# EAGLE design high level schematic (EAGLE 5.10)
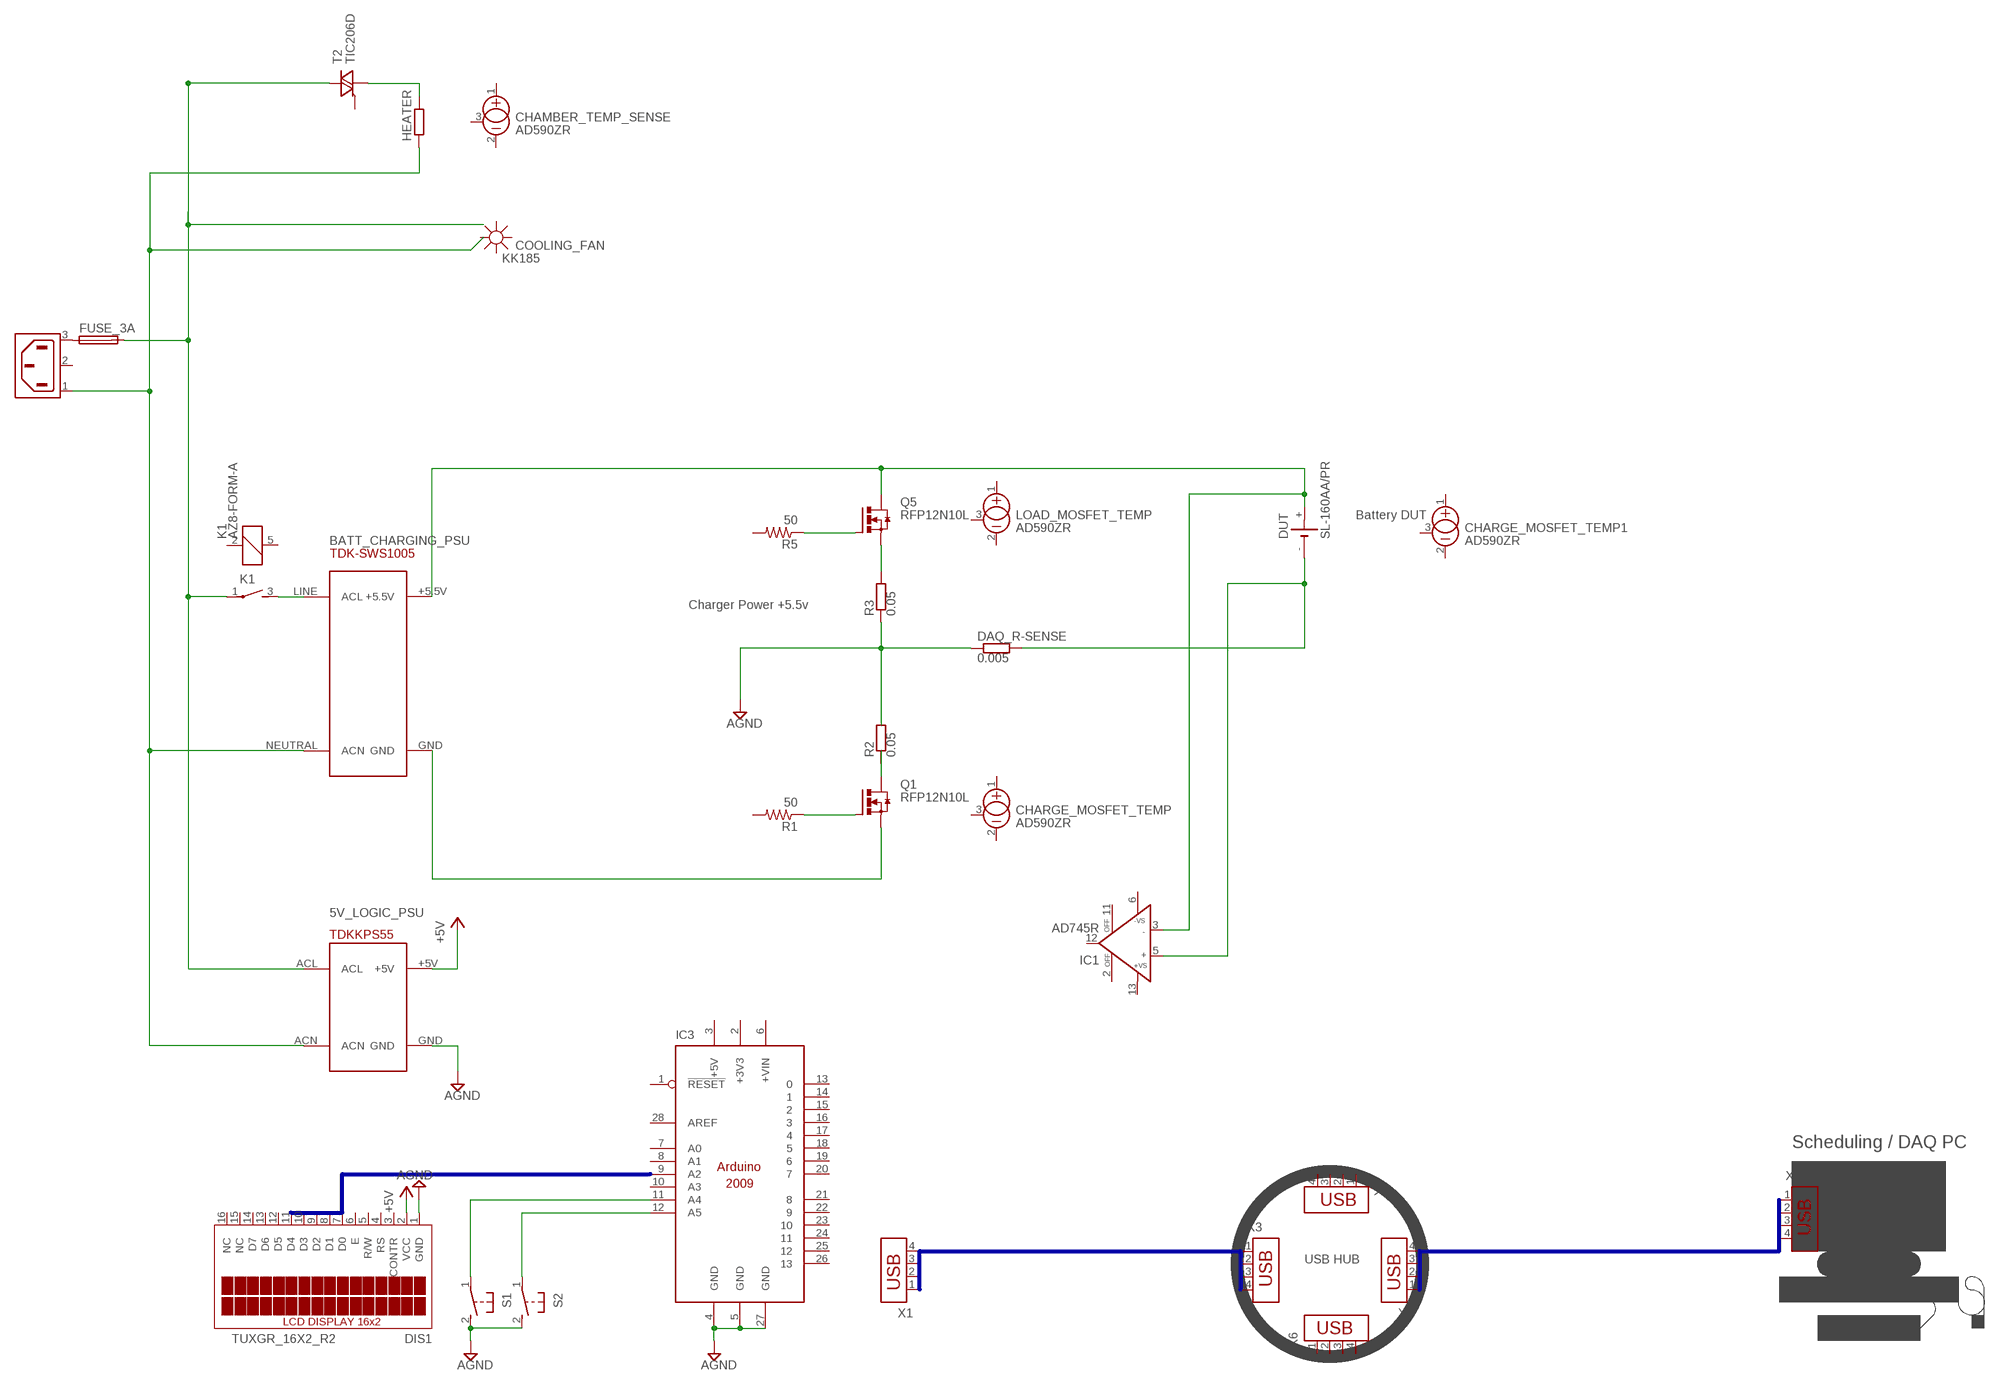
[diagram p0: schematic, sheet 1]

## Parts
5V_LOGIC_PSU  TDKKPS55  [TDKKPS55]
BATT_CHARGING_PSU  TDK-SWS1005  [TDK-SWS1005]
CHAMBER_TEMP_SENSE  AD590ZR  [TO92]
CHARGE_MOSFET_TEMP  AD590ZR  [TO92]
CHARGE_MOSFET_TEMP1  AD590ZR  [TO92]
COOLING_FAN  KK185  [KK185]
DAQ_R-SENSE  0.005  BVS  [BVS]
DIS1  TUXGR_16X2_R2  [TUXGR_16X2_R2]
DUT  SL-160AA/PR  [SL-160AA/PR]
FUSE_3A  KS9V  [KS9V]
HEATER  R-EU_0204/7  [0204/7]
IC1  AD745R  [SOIC16R]
IC3  ARDUINO2009_11  [ARDUINO2009_1]
K1  AZ8-FORM-A  [AZ8]
LOAD_MOSFET_TEMP  AD590ZR  [TO92]
Q1  RFP12N10L  [TO220-W/657-20ABP]
Q5  RFP12N10L  [TO220-W/657-20ABP]
R1  50  R-US_0207/10  [0207/10]
R2  0.05  BVS  [BVS]
R3  0.05  BVS  [BVS]
R5  50  R-US_0207/10  [0207/10]
S1  31-XX  [B3F-31XX]
S2  31-XX  [B3F-31XX]
T2  TIC206D  [TO220BV]
X1  USB-787616  [USB]
X2  6ESRM-P  [6ESRM-P]
X3  USB-787616  [USB]
X4  USB-787616  [USB]
X5  USB-787616  [USB]
X6  USB-787616  [USB]
X7  USB-787616  [USB]

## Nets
+5V: 5V_LOGIC_PSU.+5V DIS1.2(VCC)
AGND: 5V_LOGIC_PSU.GND DAQ_R-SENSE.2 DIS1.1(GND) IC3.4(GND) IC3.5(GND) IC3.27(GND) R3.2 S1.2(S) S2.2(S)
N$1: BATT_CHARGING_PSU.+5.5V DUT.+ IC1.3(IN-) Q5.2(D)
N$2: Q5.3(S) R3.1
N$3: BATT_CHARGING_PSU.LINE(ACL) K1.3(-1:S)
N$4: HEATER.2 T2.T1(A1)
N$5: DAQ_R-SENSE.1 DUT.- IC1.5(IN+)
N$6: Q1.2(D)
N$7: FUSE_3A.1 X2.3(AC2)
N$8: BATT_CHARGING_PSU.GND Q1.3(S)
N$9: 5V_LOGIC_PSU.ACL FUSE_3A.2 K1.1(-1:P) T2.T2(A2)
N$10: Q1.1(G) R1.1
N$11: Q5.1(G) R5.1
N$12: IC3.11(A4) S1.1(P)
N$13: 5V_LOGIC_PSU.ACN BATT_CHARGING_PSU.NEUTRAL(ACN) HEATER.1 X2.1(AC1)
N$14: IC3.12(A5) S2.1(P)
Unconnected: CHAMBER_TEMP_SENSE.1(+) CHAMBER_TEMP_SENSE.2(-) CHAMBER_TEMP_SENSE.3(CAN) CHARGE_MOSFET_TEMP1.1(+) CHARGE_MOSFET_TEMP1.2(-) CHARGE_MOSFET_TEMP1.3(CAN) CHARGE_MOSFET_TEMP.1(+) CHARGE_MOSFET_TEMP.2(-) CHARGE_MOSFET_TEMP.3(CAN) DIS1.3(CONTR) DIS1.4(RS) DIS1.5(R/W) DIS1.6(E) DIS1.7(D0) DIS1.8(D1) DIS1.9(D2) DIS1.10(D3) DIS1.11(D4) DIS1.12(D5) DIS1.13(D6) DIS1.14(D7) DIS1.15(NC) DIS1.16(NC) IC1.2(OFF) IC1.6(-VS) IC1.11(OFF) IC1.12(OUT) IC1.13(+VS) IC3.1(!RESET) IC3.6(+VIN) IC3.7(A0) IC3.8(A1) IC3.9(A2) IC3.10(A3) IC3.13 IC3.14 IC3.15 IC3.16 IC3.17 IC3.18 IC3.19 IC3.20 IC3.21 IC3.22 IC3.23 IC3.24 IC3.25 IC3.26 IC3.28(AREF) K1.2 K1.5 LOAD_MOSFET_TEMP.1(+) LOAD_MOSFET_TEMP.2(-) LOAD_MOSFET_TEMP.3(CAN) R1.2 R2.1 R2.2 R5.2 T2.G X1.1 X1.2 X1.3 X1.4 X2.2(SH) X3.1 X3.2 X3.3 X3.4 X4.1 X4.2 X4.3 X4.4 X5.1 X5.2 X5.3 X5.4 X6.1 X6.2 X6.3 X6.4 X7.1 X7.2 X7.3 X7.4

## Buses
B$1
B$2
B$3

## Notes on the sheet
- Battery DUT
- Charger Power +5.5v
- Scheduling / DAQ PC
- USB HUB

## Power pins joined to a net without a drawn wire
+3V3: IC3.2(+3V3)
+5V: IC3.3(+5V)

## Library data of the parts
5V_LOGIC_PSU = NEWPARTS:TDKKPS55
BATT_CHARGING_PSU = NEWPARTS:TDK-SWS1005
CHAMBER_TEMP_SENSE CHARGE_MOSFET_TEMP CHARGE_MOSFET_TEMP1 LOAD_MOSFET_TEMP = linear:AD590ZR: TEMPERATURE SENSOR current output
COOLING_FAN = heatsink:KK185: HEATSINK
DAQ_R-SENSE R2 R3 = resistor-shunt:BVS: SMD SHUNT RESISTOR
DIS1 = display-lcd:TUXGR_16X2_R2: Tuxgraphics LCD display 16x2 characters reflective, without background light Source: tuxgr_12x2_r2.pdf
DUT = battery:SL-160AA/PR: LI BATTERY Sonnenschein
FUSE_3A = fuse:KS9V: FUSE HOLDER
HEATER = resistor:R-EU_: RESISTOR, European symbol
IC1 = analog-devices:AD745: Ultralow Noise, High Speed, BiFET Op Amp Course: http://www.analog.com/static/imported-files/data_sheets/AD745.pdf
IC3 = arduino:ARDUINO2009_1: The Arduino Duemilanove ("2009") is a microcontroller board based on the ATmega168 or ATmega328. - 14 digital input/output pins (of which 6 can be used as PWM outputs) - 6 analog inputs, a 16 MHz crystal oscillator - USB connection - power jack - ISP header - reset button It contains everything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
K1 = relay:AZ8-FORM-A: MINIATURE PC BOARD RELAY Form A Source: www.azettler.com .. AZ8-1ch-12DSE.PDF
Q1 Q5 = NEWPARTS:RFP12N10L: N-Channel Power MOSFET 100V; 12A; 0,2Ohm< Logic Level
R1 R5 = rcl:R-US_: RESISTOR, American symbol
S1 S2 = switch-omron:31-XX: OMRON SWITCH
T2 = triac:TIC206: TRIAC Source: http://www.bourns.com/pdfs/tic206.pdf
X1 X3-X7 = con-amp:USB-787616: AMP connector
X2 = con-tycoelectronics:6ESRM-P: AC Connector 120/250 VAC Source: http://catalog.tycoelectronics.com .. ENG_DS_1654001_1099_SR_0406.pdf

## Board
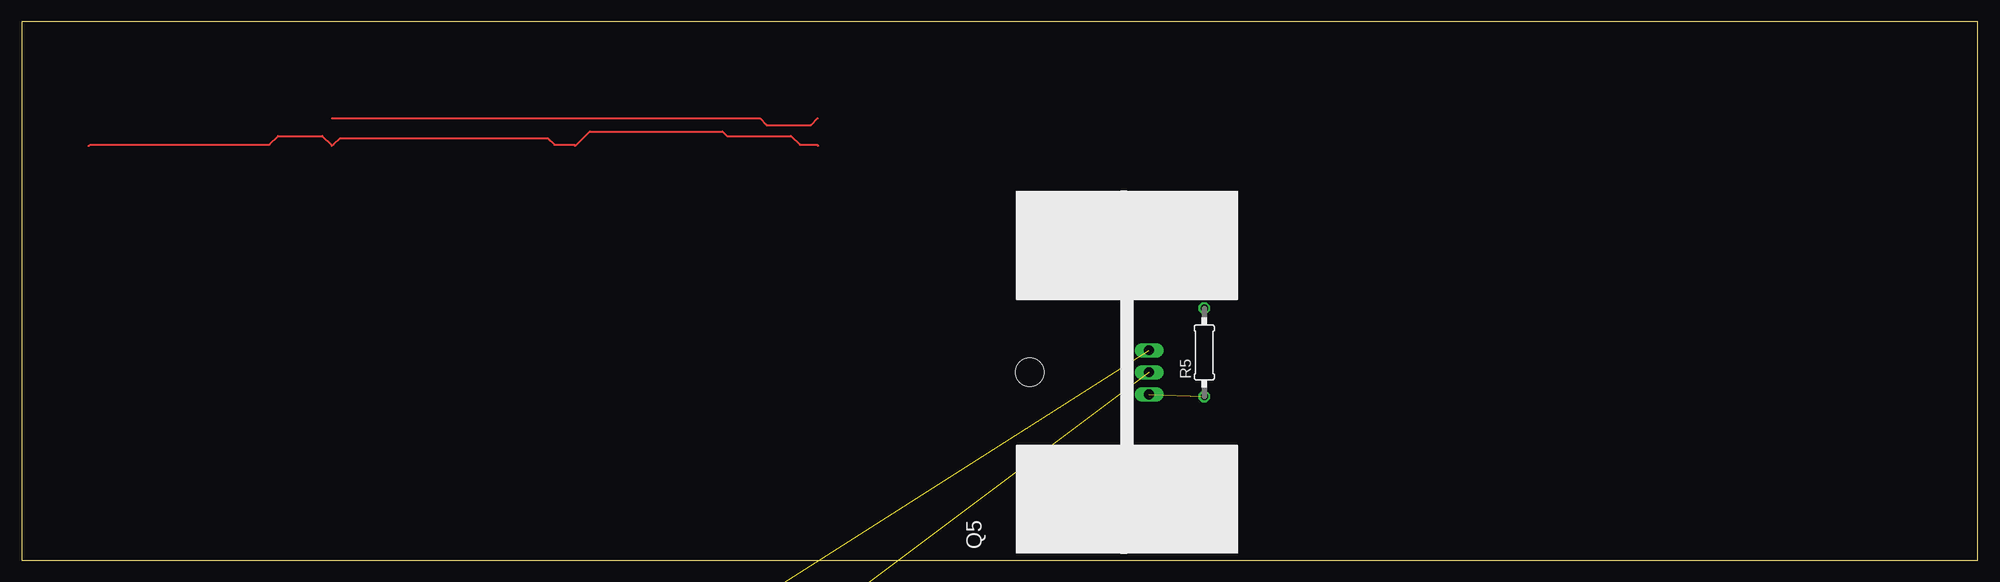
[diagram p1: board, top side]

Size 224.77 x 61.9 mm. Coordinates in mm from the lower left corner, seen from the top.
Outline: 0,0 224.77,0 224.77,61.9 0,61.9 0,0
Copper layers (1*16): Top 0.035mm / dielectric 1.5mm / Bottom 0.035mm
Design rules "default *": minimum track width 10mil, minimum drill 24mil, track to track 10mil, track to pad 10mil, pad to pad 10mil, via to via 10mil, smd to smd 10mil, copper to edge 40mil, drill to drill 10mil, minimum pad ring 10mil, minimum via ring 8mil, stop-mask expansion 4mil, vias tented up to drill 0mil, thermal gap 10mil

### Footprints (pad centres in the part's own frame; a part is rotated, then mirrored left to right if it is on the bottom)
TDKKPS55 = drill 1.1 square: +5V 51,12.5; ACL 4,5; ACN 4,22.5; GND 51,32.5
TDK-SWS1005 = drill 0.8 square: +5.5V 0,-1.27; GND 0,-3.81; LINE 0,5.08; NEUTRAL 0,2.54
TO92 = drill 0.813 octagon: 1 -1.27,0; 2 0,1.905; 3 1.27,0
BVS = smd 2.7 x 6.2: 1 -4.14,0; 2 4.14,0
TUXGR_16X2_R2 = drill 1 pad 1.676 round: 1 -32,15.5; 2 -29.46,15.5; 3 -26.92,15.5; 4 -24.38,15.5; 5 -21.84,15.5; 6 -19.3,15.5; 7 -16.76,15.5; 8 -14.22,15.5; 9 -11.68,15.5; 10 -9.14,15.5; 11 -6.6,15.5; 12 -4.06,15.5; 13 -1.52,15.5; 14 1.02,15.5; 15 3.56,15.5; 16 6.1,15.5 | hole 2.5: -37.5,-15.5; 37.5,-15.5; -37.5,15.5; 37.5,15.5
SL-160AA/PR = drill 1.321 pad 3.15 octagon: + 25.273,0; - -25.4,0
KS9V = drill 1.321 pad 2.54 long: 1 0,3.81; 2 0,-3.81
0204/7 = drill 0.813 octagon: 1 -3.81,0; 2 3.81,0
SOIC16R = smd 0.6 x 2.2: 1 -4.445,-4.775; 2 -3.175,-4.775; 3 -1.905,-4.775; 4 -0.635,-4.775; 5 0.635,-4.775; 6 1.905,-4.775; 7 3.175,-4.775; 8 4.445,-4.775; 9 4.445,4.8; 10 3.175,4.8; 11 1.905,4.8; 12 0.635,4.8; 13 -0.635,4.8; 14 -1.905,4.8; 15 -3.175,4.8; 16 -4.445,4.8
ARDUINO2009_1 = drill 1.016 long: 1 33.02,2.54; 2 35.56,2.54; 3 38.1,2.54; 4 40.64,2.54; 5 43.18,2.54; 6 45.72,2.54; 7 50.8,2.54; 8 53.34,2.54; 9 55.88,2.54; 10 58.42,2.54; 11 60.96,2.54; 12 63.5,2.54; 13 63.5,50.8; 14 60.96,50.8; 15 58.42,50.8; 16 55.88,50.8; 17 53.34,50.8; 18 50.8,50.8; 19 48.26,50.8; 20 45.72,50.8; 21 41.656,50.8; 22 39.116,50.8; 23 36.576,50.8; 24 34.036,50.8; 25 31.496,50.8; 26 28.956,50.8; 27 26.416,50.8; 28 23.876,50.8 | hole 3.2: 15.24,50.8; 66.04,35.56; 66.04,7.62 | hole 2: 55.17,27.114
AZ8 = drill 1.4 pad 2 round: 1 8.89,6.35; 2 -3.81,6.35; 3 -8.89,-1.27; 4 -3.81,-6.35; 5 -8.89,6.35
TO220-W/657-20ABP = drill 1.118 long: 1 -2.54,-2.54; 2 0,-2.54; 3 2.54,-2.54 | drill 2.8 pad 6.452 round: P$1 -12.7,0; P$2 12.7,0 | hole 3.302: 0,11.176
0207/10 = drill 0.813 octagon: 1 -5.08,0; 2 5.08,0
B3F-31XX = drill 1.016 octagon: 1 -2.261,-1.245; 2 2.261,-1.245 | drill 1.499 pad 2.159 round: 3 -3.505,1.245; 4 3.505,1.245
TO220BV = drill 1.016 long: G 2.54,-2.54; T1 -2.54,-2.54; T2 0,-2.54
USB = drill 1 round: 1 -3.5,12.99; 2 -1,12.99; 3 1,12.99; 4 3.5,12.99 | hole 2.3: -6.57,10.28; 6.57,10.28
6ESRM-P = drill 1.6 pad 2.6 round: 1 -9.1,9.7; 2 0,9.7; 3 9.1,9.7 | hole 3.6: -20,0; 20,0

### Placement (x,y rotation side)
5V_LOGIC_PSU  not placed on the board
BATT_CHARGING_PSU  not placed on the board
CHAMBER_TEMP_SENSE  not placed on the board
CHARGE_MOSFET_TEMP  not placed on the board
CHARGE_MOSFET_TEMP1  not placed on the board
COOLING_FAN  not placed on the board
DAQ_R-SENSE  not placed on the board
DIS1  not placed on the board
DUT  not placed on the board
FUSE_3A  not placed on the board
HEATER  not placed on the board
IC1  not placed on the board
IC3  not placed on the board
K1  not placed on the board
LOAD_MOSFET_TEMP  not placed on the board
Q1  not placed on the board
Q5  127,21.59 90 top
R1  not placed on the board
R2  not placed on the board
R3  not placed on the board
R5  135.89,23.88 90 top
S1  not placed on the board
S2  not placed on the board
T2  not placed on the board
X1  not placed on the board
X2  not placed on the board
X3  not placed on the board
X4  not placed on the board
X5  not placed on the board
X6  not placed on the board
X7  not placed on the board

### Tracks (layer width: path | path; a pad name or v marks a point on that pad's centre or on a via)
+5V  (2 unrouted)
AGND  (8 unrouted)
N$1  (3 unrouted)
N$2  (1 unrouted)
N$3  (1 unrouted)
N$4  (1 unrouted)
N$5  (2 unrouted)
N$7  (1 unrouted)
N$8  (1 unrouted)
N$9  (3 unrouted)
N$10  (1 unrouted)
N$11  (1 unrouted)
N$12  (1 unrouted)
N$13  (3 unrouted)
N$14  (1 unrouted)
NC
  Top 0.254: 91.5,47.62 91.44,47.75 89.41,47.75 88.39,48.77 81.03,48.77 80.52,49.28 65.28,49.28 63.75,47.75 63.56,47.62 63.5,47.75 61.21,47.75 60.45,48.51 36.58,48.51 35.81,47.75 35.62,47.62 35.56,47.75 34.54,48.77 29.46,48.77 28.45,47.75 7.87,47.75 7.68,47.62
NC2
  Top 0.254: 35.62,50.8 84.84,50.8 85.6,50.04 90.68,50.04 91.44,50.8 91.5,50.8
